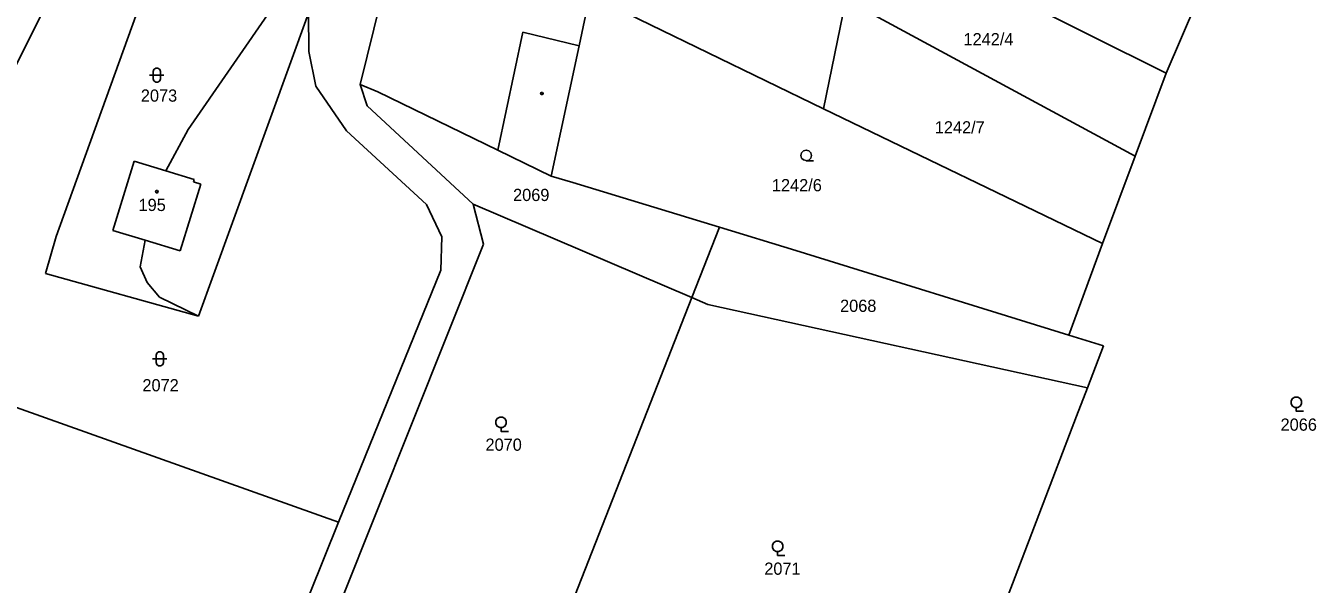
# Model space of a CAD drawing. Extents: x -802857 to -799647, y -1020285 to -1015884.
# Drawn here: x -801407 to -801227.4, y -1018091.1 to -1018013.3 of the extents above; entities that cross this region are included whole.
import ezdxf

# ---------------------------------------------------------------- set-up
doc = ezdxf.new("R2010")
doc.units = 0
for name, color, linetype in [('Default', 7, 'Continuous'), ('KN_HRANICE', 7, 'Continuous'), ('KN_KULTURY', 7, 'Continuous'), ('KN_PARCELY', 7, 'Continuous'), ('KN_SLUCKY', 7, 'Continuous')]:
    doc.layers.add(name, color=color, linetype=linetype)

# ---------------------------------------------------------------- blocks, each defined once
blk = doc.blocks.new('304')
at = {"layer": 'Default'}
blk.add_lwpolyline([(0, 0), (-0.38, 0.1), (-0.65, 0.37), (-0.75, 0.74), (-0.65, 1.11), (-0.38, 1.38), (-0.01, 1.48), (0.36, 1.38), (0.63, 1.11), (0.73, 0.73), (0.63, 0.35), (0.36, 0.08), (-0.02, -0.02), (0.98, -0.02)], dxfattribs=at)
blk = doc.blocks.new('305')
at = {"layer": 'Default'}
blk.add_lwpolyline([(0, 0.53), (-0.19, 0.53), (-0.53, 0.72), (-0.72, 1.06), (-0.72, 1.45), (-0.53, 1.79), (-0.19, 1.98), (0.2, 1.98), (0.54, 1.79), (0.73, 1.45), (0.73, 1.06), (0.54, 0.72), (0.2, 0.53), (0.01, 0.53), (0.01, 0), (1.01, 0)], dxfattribs=at)
blk = doc.blocks.new('316')
at = {"layer": 'Default'}
for points in [[(-0.5, 1.5), (-0.4, 1.79), (-0.15, 1.97), (0.16, 1.97), (0.41, 1.79), (0.51, 1.5), (0.51, 0.5), (0.41, 0.21), (0.16, 0.03), (-0.15, 0.03), (-0.4, 0.21), (-0.5, 0.5), (-0.5, 1.5)], [(-1, 1), (0.27, 1), (1, 1)]]:
    blk.add_lwpolyline(points, dxfattribs=at)
blk = doc.blocks.new('402')
at = {"layer": 'Default'}
blk.add_lwpolyline([(0.09, 0.15), (0.18, 0), (0.09, -0.15), (-0.09, -0.15), (-0.18, 0), (-0.09, 0.15), (0.09, 0.15)], dxfattribs=at)

msp = doc.modelspace()

# ---------------------------------------------------------------- linework, layer by layer
at = {"layer": 'KN_HRANICE'}
for p, q in [((-801290.6, -1017998.81), (-801248.25, -1018019.94)), ((-801403.7, -1018009.39), (-801421.73, -1018045.46)), ((-801391.12, -1018010.28), (-801402.79, -1018042.66)), ((-801360.46, -1018021.5), (-801357.6, -1018009.88)), ((-801328.49, -1018009.09), (-801329.99, -1018016.14)), ((-801328.49, -1018009.09), (-801295.95, -1018024.91)), ((-801292.85, -1018009.68), (-801295.95, -1018024.91)), ((-801292.85, -1018009.68), (-801252.58, -1018031.49)), ((-801248.25, -1018019.94), (-801243.96, -1018010)), ((-801384.44, -1018027.77), (-801372.53, -1018010.6)), ((-801367.65, -1018011.57), (-801380.88, -1018048.02)), ((-801367.61, -1018016.94), (-801367.65, -1018011.57)), ((-801366.63, -1018021.76), (-801367.61, -1018016.94)), ((-801329.99, -1018016.14), (-801333.87, -1018034.28)), ((-801252.58, -1018031.49), (-801248.25, -1018019.94)), ((-801362.36, -1018027.96), (-801366.63, -1018021.76)), ((-801358.01, -1018022.56), (-801360.46, -1018021.5)), ((-801360.46, -1018021.5), (-801359.5, -1018024.48)), ((-801341.29, -1018030.67), (-801358.01, -1018022.56)), ((-801359.5, -1018024.48), (-801344.72, -1018038.17)), ((-801295.95, -1018024.91), (-801257.13, -1018043.64)), ((-801387.54, -1018033.54), (-801384.44, -1018027.77)), ((-801362.36, -1018027.96), (-801351.25, -1018038.21)), ((-801333.87, -1018034.28), (-801341.29, -1018030.67)), ((-801252.58, -1018031.49), (-801257.13, -1018043.64)), ((-801391.96, -1018032.2), (-801394.91, -1018041.83)), ((-801391.96, -1018032.2), (-801387.54, -1018033.54)), ((-801330.84, -1018035.16), (-801333.87, -1018034.28)), ((-801330.84, -1018035.16), (-801310.46, -1018041.38)), ((-801349.1, -1018042.73), (-801351.25, -1018038.21)), ((-801344.72, -1018038.17), (-801343.28, -1018043.75)), ((-801344.72, -1018038.17), (-801314.3, -1018051.18)), ((-801402.79, -1018042.66), (-801404.28, -1018047.83)), ((-801394.91, -1018041.83), (-801390.42, -1018043.18)), ((-801349.1, -1018042.73), (-801349.23, -1018047.34)), ((-801314.3, -1018051.18), (-801310.46, -1018041.38)), ((-801310.46, -1018041.38), (-801299.8, -1018044.64)), ((-801390.42, -1018043.18), (-801391.12, -1018046.89)), ((-801343.28, -1018043.75), (-801363.17, -1018093.47)), ((-801261.78, -1018056.41), (-801299.8, -1018044.64)), ((-801257.13, -1018043.64), (-801261.78, -1018056.41)), ((-801404.28, -1018047.83), (-801382.99, -1018053.78)), ((-801391.12, -1018046.89), (-801390.14, -1018049.06)), ((-801380.88, -1018048.02), (-801382.99, -1018053.78)), ((-801349.23, -1018047.34), (-801363.47, -1018082.46)), ((-801390.14, -1018049.06), (-801388.4, -1018051.14)), ((-801388.4, -1018051.14), (-801382.99, -1018053.78)), ((-801336.64, -1018108.15), (-801314.3, -1018051.18)), ((-801314.3, -1018051.18), (-801312.07, -1018052.13)), ((-801312.07, -1018052.13), (-801259.2, -1018063.73)), ((-801256.96, -1018057.9), (-801261.78, -1018056.41)), ((-801256.96, -1018057.9), (-801259.2, -1018063.73)), ((-801426.55, -1018059.97), (-801363.47, -1018082.46)), ((-801259.2, -1018063.73), (-801260.71, -1018067.67)), ((-801260.71, -1018067.67), (-801284.83, -1018130.58)), ((-801363.47, -1018082.46), (-801367.49, -1018092.36))]:
    msp.add_line(p, q, dxfattribs=at)
at = {"layer": 'KN_SLUCKY'}
for p, q in [((-801341.29, -1018030.67), (-801337.84, -1018014.22)), ((-801337.84, -1018014.22), (-801329.99, -1018016.14)), ((-801387.54, -1018033.54), (-801383.6, -1018034.74)), ((-801385.54, -1018044.65), (-801382.66, -1018035.4)), ((-801383.69, -1018035.05), (-801383.6, -1018034.74)), ((-801382.66, -1018035.4), (-801383.69, -1018035.05)), ((-801390.42, -1018043.18), (-801385.54, -1018044.65))]:
    msp.add_line(p, q, dxfattribs=at)

# ---------------------------------------------------------------- block references
at = {"layer": 'KN_KULTURY'}
for name, p in [('316', (-801388.79, -1018021.21)), ('402', (-801335.16, -1018022.76)), ('304', (-801298.35, -1018032.12)), ('402', (-801388.78, -1018036.43)), ('316', (-801388.38, -1018060.71)), ('305', (-801230.13, -1018067.01)), ('305', (-801340.85, -1018069.8)), ('305', (-801302.36, -1018087.06))]:
    msp.add_blockref(name, p, dxfattribs=at)

# ---------------------------------------------------------------- texts
at = {"layer": 'KN_PARCELY'}
for s, p in [('1242/4', (-801276.46, -1018016.06)), ('2073', (-801391.01, -1018023.91)), ('1242/7', (-801280.46, -1018028.33)), ('1242/6', (-801303.14, -1018036.38)), ('195', (-801391.33, -1018039.13)), ('2069', (-801339.18, -1018037.74)), ('2068', (-801293.65, -1018053.17)), ('2072', (-801390.79, -1018064.23)), ('2066', (-801232.31, -1018069.71)), ('2070', (-801343.02, -1018072.5)), ('2071', (-801304.2, -1018089.76))]:
    msp.add_text(s, height=1.7, dxfattribs=at).set_placement(p)

doc.saveas('drawing.dxf')
